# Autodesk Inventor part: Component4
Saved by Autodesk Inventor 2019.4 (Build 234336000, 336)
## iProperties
Created: 2019-12
Part Number: Component4
Material: Generic
Document SubType Name: Modeling
Designer: Administrator
Density: 1 g/cm^3
Appearance: Default
Title: Component4
Author: Administrator
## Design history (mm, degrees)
feature "Body1"
body "Solid1"
